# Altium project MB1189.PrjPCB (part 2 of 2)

## Sheet AUDIO2.SchDoc: Audio Codec and Microphone MEMS
size A4; Date: 9/24/2014; Author: P.A.; CompanyName: STMicroelectronics; Organization: Microcontrollers Division; Address1: 12, Rue Jules HOROWITZ; Address2: 38019 Grenoble; Address3: FRANCE; DocumentNumber: MB1189; Revision: B-07; SheetNumber: 6; SheetTotal: 12; Project: STM32F469I-DISCO
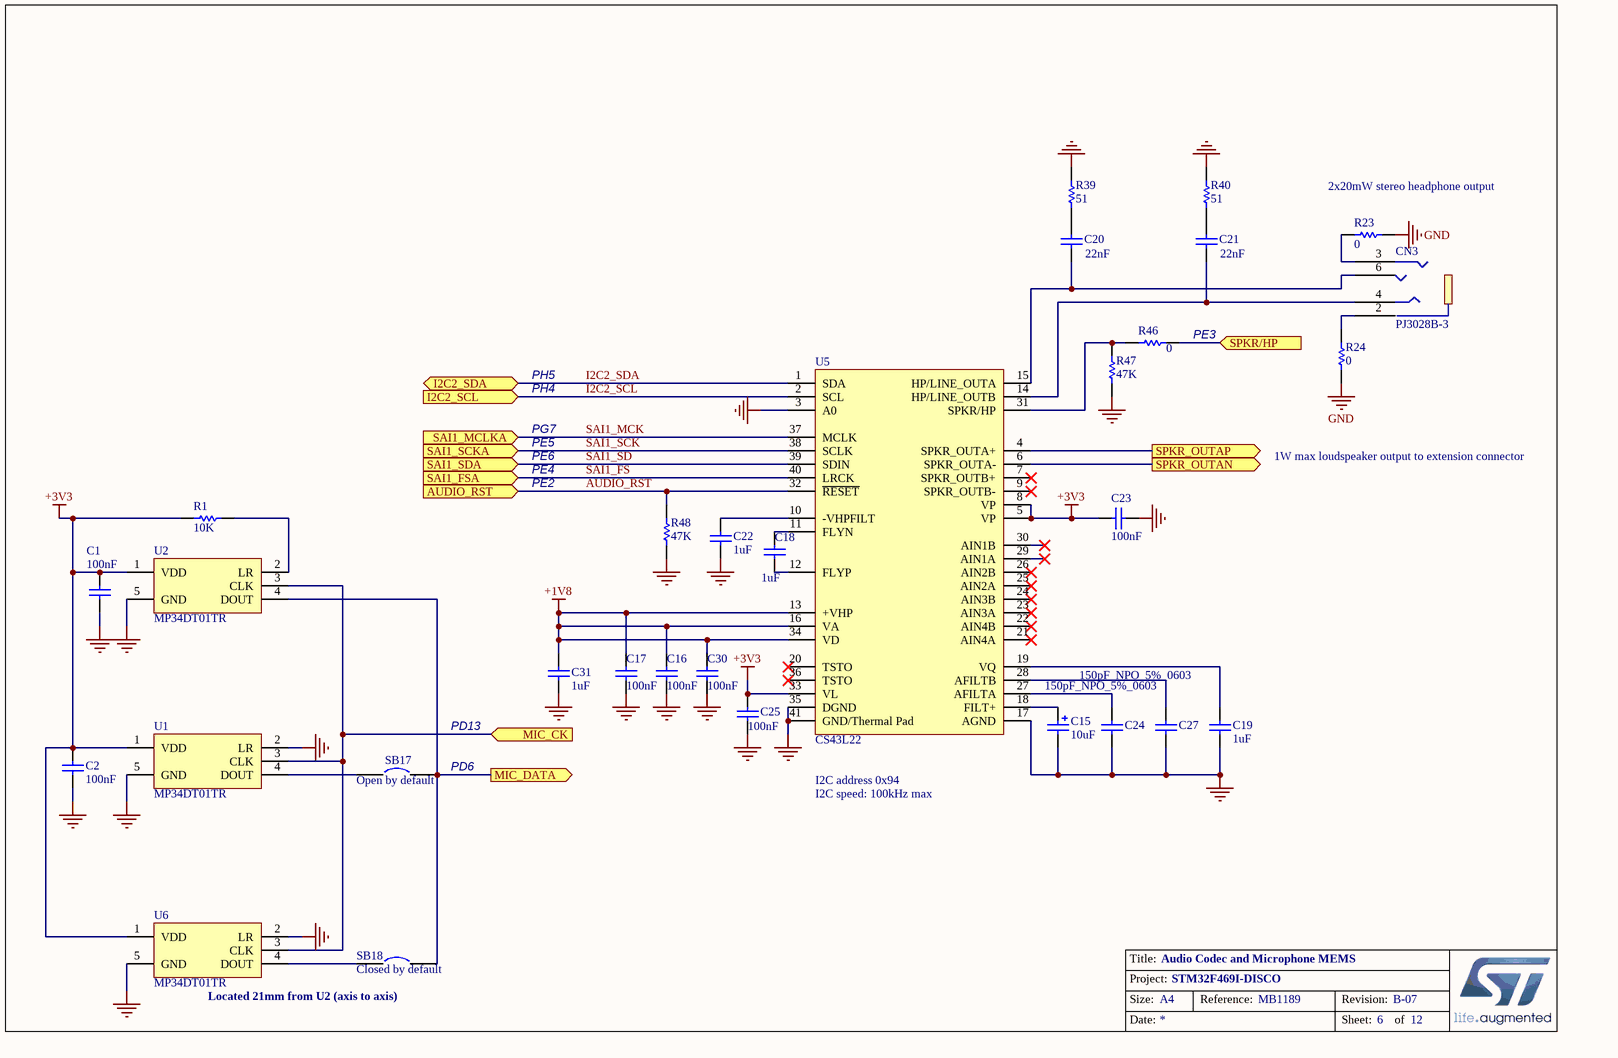
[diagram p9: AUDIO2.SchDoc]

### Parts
C1  100nF  [0402C]
C2  100nF  [0402C]
C15  10uF  [TAN-A]
C16  100nF  [0402C]
C17  100nF  [0402C]
C18  1uF  [0603C]
C19  1uF  [0603C]
C20  22nF  [0603C]
C21  22nF  [0603C]
C22  1uF  [0603C]
C23  100nF  [0402C]
C24  150pF_NPO_5%_0603  [0603C]
C25  100nF  [0402C]
C27  150pF_NPO_5%_0603  [0603C]
C30  100nF  [0402C]
C31  1uF  [0603C]
CN3  PJ3028B-3  [PJ3028B]
R1  10K  [0603R]
R23  0  [0603R]
R24  0  [0603R]
R39  51  [0402R]
R40  51  [0402R]
R46  0  [0603R]
R47  47K  [0603R]
R48  47K  [0603R]
SB17  Open by default  [SB_0603]
SB18  Closed by default  [SB_0603]
U1  MP34DT01TR  [MP34DT01TR]
U2  MP34DT01TR  [MP34DT01TR]
U5  CS43L22  [QFN40_0R5_6X6]
U6  MP34DT01TR  [MP34DT01TR]

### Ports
AUDIO_RST (in), I2C2_SCL (in), I2C2_SDA (bidir), MIC_CK (in), MIC_DATA (out), SAI1_FSA (in), SAI1_MCLKA (in), SAI1_SCKA (in), SAI1_SDA (in), SPKR/HP (in), SPKR_OUTAN (out), SPKR_OUTAP (out)

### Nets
+1V8: C16.1 C17.1 C30.1 C31.1 U5.13(+VHP) U5.16(VA) U5.34(VD)
+3V3: C1.2 C2.2 C23.2 C25.1 R1.2 U1.1(VDD) U2.1(VDD) U5.5(VP) U5.8(VP) U5.33(VL) U6.1(VDD)
GND: C1.1 C2.1 C15.2 C16.2 C17.2 C19.1 C22.1 C23.1 C24.1 C25.2 C27.1 C30.2 C31.2 R23.2 R24.2 R39.2 R40.2 R47.2 R48.1 U1.2(LR) U1.5(GND) U2.5(GND) U5.3(A0) U5.17(AGND) U5.35(DGND) U5.41(GND/Thermal_Pad) U6.2(LR) U6.5(GND)
AUDIO_RST: R48.2 U5.32(~{RESET}) ; port AUDIO_RST
I2C2_SCL: U5.2(SCL) ; port I2C2_SCL
I2C2_SDA: U5.1(SDA) ; port I2C2_SDA
PD6: SB17.2 SB18.2 U2.4(DOUT) ; port MIC_DATA
PE3: R46.2 ; port SPKR/HP
SAI1_FS: U5.40(LRCK) ; port SAI1_FSA  [project net PE4]
SAI1_MCK: U5.37(MCLK) ; port SAI1_MCLKA  [project net PG7]
SAI1_SCK: U5.38(SCLK) ; port SAI1_SCKA  [project net PE5]
SAI1_SD: U5.39(SDIN) ; port SAI1_SDA  [project net PE6]
SPKR_OUTAN: U5.6(SPKR_OUTA-) ; port SPKR_OUTAN
SPKR_OUTAP: U5.4(SPKR_OUTA+) ; port SPKR_OUTAP
NetC15_1: C15.1 U5.18(FILT+)
NetC18_1: C18.1 U5.11(FLYN)
NetC18_2: C18.2 U5.12(FLYP)
NetC19_2: C19.2 U5.19(VQ)
NetC20_1: C20.1 CN3.6 U5.15(HP/LINE_OUTA)
NetC20_2: C20.2 R39.1
NetC21_1: C21.1 CN3.4 U5.14(HP/LINE_OUTB)
NetC21_2: C21.2 R40.1
NetC22_2: C22.2 U5.10(-VHPFILT)
NetC24_2: C24.2 U5.27(AFILTA)
NetC27_2: C27.2 U5.28(AFILTB)
NetCN3_2: CN3.2 R24.1
NetCN3_3: CN3.3 R23.1
NetR1_1: R1.1 U2.2(LR)
NetR46_1: R46.1 R47.1 U5.31(SPKR/HP)
NetR87_1: U1.3(CLK) U2.3(CLK) U6.3(CLK) ; port MIC_CK
NetSB17_1: SB17.1 U1.4(DOUT)
NetSB18_1: SB18.1 U6.4(DOUT)

Not connected (* = marked no-connect by the designer): U5 7(SPKR_OUTB+)* 9(SPKR_OUTB-)* 20(TSTO)* 21(AIN4A)* 22(AIN4B)* 23(AIN3A)* 24(AIN3B)* 25(AIN2A)* 26(AIN2B)* 29(AIN1A)* 30(AIN1B)* 36(TSTO)*

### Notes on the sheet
- (near R23) 2x20mW stereo headphone output
- PH5
- (near R46) PE3
- PE5
- PG7
- PH4
- PE6
- PE4
- PE2
- 1W max loudspeaker output to extension connector
- PD13
- (near SB17) PD6
- I2C address 0x94
- I2C speed: 100kHz max
- Located 21mm from U2 (axis to axis)

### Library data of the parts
C1 C2 = Cap: Capacitor; Value: 10nF; Ordered by: Subcon
C15 = Cap Pol1: Polarized Capacitor (Radial); Ordered by: Subcon
C16-C19 C22 C23 C25 C30 C31 = CAP: Capacitor; Value: 100pF; Ordered by: Subcon
C20 C21 = Cap_22nF_X7R_10%_0603: Capacitor,22nF,50V,X7R,10%,0603,YAGEO; Manuf_Part_1: CC0603KRX7R9BB223; Ordered by: Subcon
C24 C27 = Cap_150pF_NPO_5%_0603: Capacitor,150pF,50V,NPO,5%,0603,YAGEO; Order: CC0603JRNPO9BN151; Ordered by: Subcon
CN3 = PJ3028B-3: Manuf_1: QIAOD; Ordered by: Subcon; Silkscreen: AUDIO JACK
R1 = Res_0_5%_0402: Resistor; Manuf_Part_1: RC0402JR-070RL; Manuf_1: YAGEO; Description: Resistor,0,0402,5%,YAGEO; Value: 0; Order: 2363467; Ordered by: Subcon
R23 R24 R46-R48 = Res1: Resistor; Value: 1K; Ordered by: Subcon
R39 R40 = Res_51_1%_0402: Resistor; Manuf_Part_1: RC0402FR-0751RL; Manuf_1: YAGEO; Description: Resistor,51,0402,1%,YAGEO; Order: 311-51.0LRTR-ND; Ordered by: Subcon
SB17 = Circuit Breaker: Ordered by: Subcon; Comments: Solder bridge; Fitted: NO
SB18 = Circuit Breaker: Ordered by: Subcon; Comments: Solder bridge
U1 U2 U6 = MP34DT01TR: MEMS audio sensor; Ordered by: ST; Ref St: 9188008; ECCN_US/EU: EAR99/NEC
U5 = CS43L22: Low Power, Stereo DAC w/Headphone & Speaker Amps; Manuf_1: Cirrus; Order: CS43L22-CNZ; ECCN_US/EU: EAR99/NEC; Ordered by: Subcon

## Sheet USB_OTG_FS.SchDoc: USB_OTG_FS
size A4; Date: 9/24/2014; Author: P.A.; CompanyName: STMicroelectronics; Organization: Microcontrollers Division; Address1: 12, Rue Jules HOROWITZ; Address2: 38019 Grenoble; Address3: FRANCE; DocumentNumber: MB1189; Revision: B-07; SheetNumber: 10; SheetTotal: 12; Project: STM32F469I-DISCO
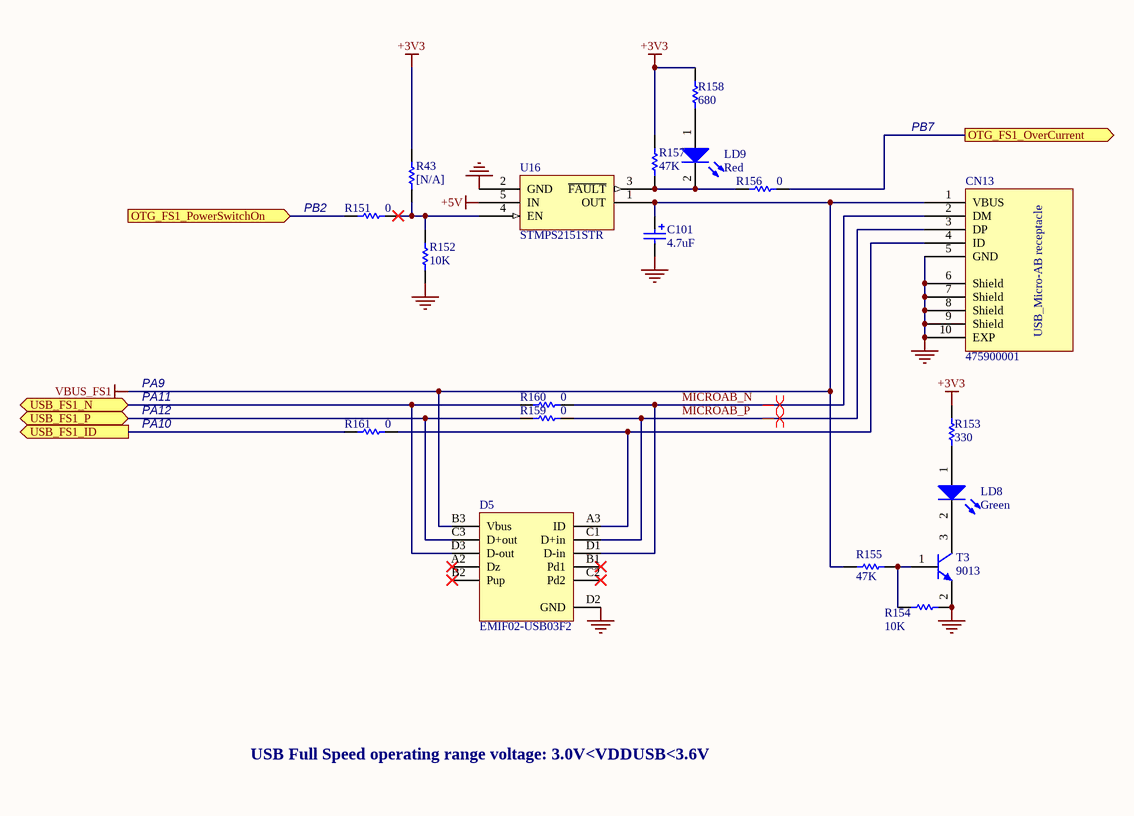
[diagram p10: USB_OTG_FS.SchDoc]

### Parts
C101  4.7uF  [TAN-A]
CN13  475900001  [MOLEX_47590001]
D5  EMIF02-USB03F2  [BGA11_0R5_1R57X2R07]
LD8  Green  [0603D]
LD9  Red  [0603D]
R43  [N/A]  [0603R]
R151  0  [0603R]
R152  10K  [0402R]
R153  330  [0603R]
R154  10K  [0603R]
R155  47K  [0603R]
R156  0  [0603R]
R157  47K  [0603R]
R158  680  [0603R]
R159  0  [0603R]
R160  0  [0603R]
R161  0  [0603R]
T3  9013  [SOT-23]
U16  STMPS2151STR  [SOT23-5]

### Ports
OTG_FS1_OverCurrent (out), OTG_FS1_PowerSwitchOn (in), USB_FS1_ID (out), USB_FS1_N (bidir), USB_FS1_P (bidir)

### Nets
+3V3: R43.1 R153.2 R157.1 R158.2
+5V: U16.5(IN)
GND: C101.2 CN13.5(GND) CN13.6(Shield) CN13.7(Shield) CN13.8(Shield) CN13.9(Shield) CN13.10(EXP) D5.D2(GND) R152.1 R154.1 T3.2(E) U16.2(GND)
VBUS_FS1: C101.1 CN13.1(VBUS) D5.B3(Vbus) R155.1 U16.1(OUT)
MICROAB_N: CN13.2(DM) D5.D1(D-in) R160.1
MICROAB_P: CN13.3(DP) D5.C1(D+in) R159.1
PA10: R161.2 ; port USB_FS1_ID
PB2: R151.2 ; port OTG_FS1_PowerSwitchOn
PB7: R156.1 ; port OTG_FS1_OverCurrent
USB_FS1_N: D5.D3(D-out) R160.2 ; port USB_FS1_N
USB_FS1_P: D5.C3(D+out) R159.2 ; port USB_FS1_P
NetCN13_4: CN13.4(ID) D5.A3(ID) R161.1
NetLD8_1: LD8.1(A) R153.1
NetLD8_2: LD8.2(K) T3.3(C)
NetLD9_1: LD9.1(A) R158.1
NetLD9_2: LD9.2(K) R156.2 R157.2 U16.3(~{FAULT})
NetR43_2: R43.2 R151.1 R152.2 U16.4(EN)
NetR154_2: R154.2 R155.2 T3.1(B)

Not connected (* = marked no-connect by the designer): D5 A2(Dz)* B1(Pd1)* B2(Pup)* C2(Pd2)*

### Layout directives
differential pair: MICROAB_N, MICROAB_P

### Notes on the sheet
- PB7
- (near R151) PB2
- PA9
- PA10
- PA11
- PA12
- USB Full Speed operating range voltage: 3.0V<VDDUSB<3.6V

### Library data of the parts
C101 = Cap Pol1: Polarized Capacitor (Radial); Value: 47uF; Ordered by: Subcon
CN13 = 475900001: Manuf_1: MOLEX; Ordered by: Subcon; Silkscreen: USB USER
D5 = EMIF02-USB03F2: 2-line IPAD, EMI filter including ESD protection; Manuf_1: ST; ECCN_US/EU: EAR99/NEC; Ref St: 9179037
LD8 = LED2: Typical RED, GREEN, YELLOW, AMBER GaAs LED; Ordered by: Subcon; ECCN_US/EU: EAR99/NEC; Silkscreen: VBUS
LD9 = LED2: Typical RED, GREEN, YELLOW, AMBER GaAs LED; Ordered by: Subcon; ECCN_US/EU: EAR99/NEC; Silkscreen: FAULT
R43 = Res1: Resistor; Value: 1K; Ordered by: Subcon; Fitted: NO
R151 R152 R156 R158-R161 = Res1: Resistor; Value: 1K; Ordered by: Subcon
R153-R155 R157 = res1: Resistor; Value: 1K; Ordered by: Subcon
T3 = NPN: NPN Bipolar Transistor; Manuf_Part_1: MMBT9013; Code - JEDEC: TO-226-AA; Ordered by: Subcon; ECCN_US/EU: EAR99/NEC
U16 = STMPS2141STR: Ordered by: ST; Ref St: 9159009; ECCN_US/EU: EAR99/NEC

## Sheet ExtensionConnector.SchDoc: Extension Connectors
size A4; Date: 9/24/2014; Author: P.A.; CompanyName: STMicroelectronics; Organization: Microcontrollers Division; Address1: 12, Rue Jules HOROWITZ; Address2: 38019 Grenoble; Address3: FRANCE; DocumentNumber: MB1189; Revision: B-07; SheetNumber: 3; SheetTotal: 12; Project: STM32F469I-DISCO
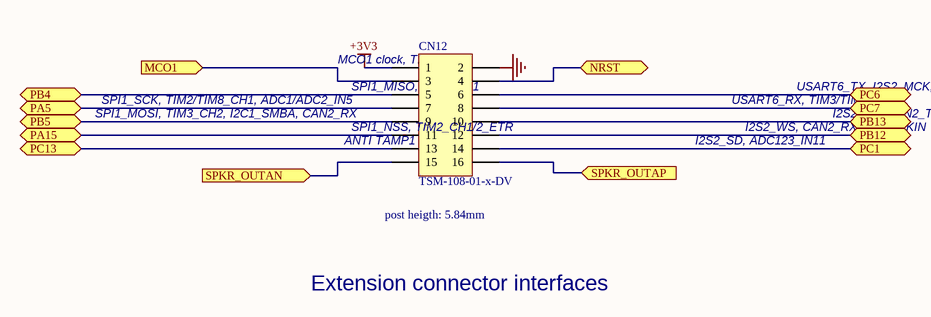
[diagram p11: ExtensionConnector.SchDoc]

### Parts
CN12  TSM-108-01-x-DV  [TSM-108-01-X-DV]

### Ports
MCO1 (in), NRST (bidir), PA5 (bidir), PA15 (bidir), PB4 (bidir), PB5 (bidir), PB12 (bidir), PB13 (bidir), PC1 (bidir), PC6 (bidir), PC7 (bidir), PC13 (bidir), SPKR_OUTAN (in), SPKR_OUTAP (in)

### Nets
+3V3: CN12.1
GND: CN12.2
NRST: CN12.4 ; port NRST
PA5: CN12.7 ; port PA5
PA8: CN12.3 ; port MCO1
PA15: CN12.11 ; port PA15
PB4: CN12.5 ; port PB4
PB5: CN12.9 ; port PB5
PB12: CN12.12 ; port PB12
PB13: CN12.10 ; port PB13
PC1: CN12.14 ; port PC1
PC6: CN12.6 ; port PC6
PC7: CN12.8 ; port PC7
PC13: CN12.13 ; port PC13
SPKR_OUTAN: CN12.15 ; port SPKR_OUTAN
SPKR_OUTAP: CN12.16 ; port SPKR_OUTAP

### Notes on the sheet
- MCO1 clock, TIM1_CH1
- SPI1_MISO, TIM3_CH1
- USART6_TX, I2S2_MCK, TIM3/TIM8_CH1
- SPI1_MOSI, TIM3_CH2, I2C1_SMBA, CAN2_RX
- SPI1_SCK, TIM2/TIM8_CH1, ADC1/ADC2_IN5
- ANTI TAMP1
- SPI1_NSS, TIM2_CH1/2_ETR
- I2S2_SD, ADC123_IN11
- USART6_RX, TIM3/TIM8_CH2
- I2S2_WS, CAN2_RX, TIM1_BKIN
- I2S2_CK, CAN2_TX, USART3_CTS, TIM1_CH1N
- (near CN12) post heigth: 5.84mm
- Extension connector interfaces

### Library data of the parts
CN12 = Header 8X2: Header, 8-Pin, Dual row; Manuf_1: SAMTEC; Ordered by: Subcon; Silkscreen: EXT

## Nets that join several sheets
+1V8: Power (C32.1 U8.2 U8.4), AUDIO2 (7 pins)
+3V3: Memory (28 pins), Peripherals (15 pins), Power (C41.1 JP5.1 SB8.2 U8.3), ST_LINK_V2-1 (R33.1), MCU (7 pins), Arduino_ Connectors (CN6.2 CN6.4), DSI_LCD (9 pins), QSPI (C62.1 R55.2 U12.8), AUDIO2 (11 pins), USB_OTG_FS (R43.1 R153.2 R157.1 R158.2), ExtensionConnector (CN12.1)
+5V: Power (6 pins), ST_LINK_V2-1 (D1.1), Arduino_ Connectors (CN6.5), DSI_LCD (L1.1 SB13.1), USB_OTG_FS (U16.5)
E5V: Power (C35.1 JP2.1 U10.2 U10.4), ST_LINK_V2-1 (D2.1)
GND: MB1189 (H1.1 H2.1 H3.1 H4.1), Memory (28 pins), Peripherals (7 pins), Power (12 pins), ST_LINK_V2-1 (34 pins), MCU (57 pins), Arduino_ Connectors (5 pins), DSI_LCD (12 pins), QSPI (C62.2 U12.4), AUDIO2 (28 pins), USB_OTG_FS (12 pins), ExtensionConnector (CN12.2)
U5V_ST_LINK: Power (JP2.3), ST_LINK_V2-1 (C14.2 U4.6 U4.7)
VBUS_FS1: Power (JP2.5), ST_LINK_V2-1 (D3.1), MCU (U14.E15), USB_OTG_FS (5 pins)
VDD_MCU: Power (JP5.2), MCU (40 pins)
VIN: Power (C36.1 U10.3), Arduino_ Connectors (CN6.8)
VREF+: MCU (C78.2 C80.1 R123.2 U14.P1), Arduino_ Connectors (C13.2 R41.1)
A0: Memory (U11.G8), MCU (U14.D2)
A1: Memory (U11.G9), MCU (U14.E2)
A2: Memory (U11.F7), MCU (U14.G2)
A3: Memory (U11.F3), MCU (U14.H2)
A4: Memory (U11.G1), MCU (U14.J2)
A5: Memory (U11.G2), MCU (U14.K3)
A6: Memory (U11.G3), MCU (U14.M6)
A7: Memory (U11.H1), MCU (U14.N6)
A8: Memory (U11.H2), MCU (U14.P6)
A9: Memory (U11.J3), MCU (U14.M8)
A10: Memory (U11.G7), MCU (U14.N7)
A11: Memory (U11.H9), MCU (U14.M7)
A14: Memory (U11.J7), MCU (U14.N12)
A15: Memory (U11.H8), MCU (U14.N11)
AUDIO_RST: MCU (U14.A3), AUDIO2 (R48.2 U5.32)
D0: Memory (TP4.1 U11.R8), MCU (TP1.1 U14.L12)
D1: Memory (U11.N7), MCU (U14.K13)
D2: Memory (U11.R9), MCU (U14.B12)
D3: Memory (U11.N8), MCU (U14.C12)
D4: Memory (U11.P9), MCU (U14.R8)
D5: Memory (U11.M8), MCU (U14.N9)
D6: Memory (U11.M7), MCU (U14.P9)
D7: Memory (U11.L8), MCU (U14.R9)
D8: Memory (U11.L2), MCU (U14.P10)
D9: Memory (U11.M3), MCU (U14.R10)
D10: Memory (U11.M2), MCU (U14.R12)
D11: Memory (U11.P1), MCU (U14.P11)
D12: Memory (U11.N2), MCU (U14.R11)
D13: Memory (U11.R1), MCU (U14.L15)
D14: Memory (U11.N3), MCU (U14.L14)
D15: Memory (U11.R2), MCU (U14.K15)
D16: Memory (U11.E8), MCU (U14.P14)
D17: Memory (U11.D7), MCU (U14.N14)
D18: Memory (U11.D8), MCU (U14.P15)
D19: Memory (U11.B9), MCU (U14.N15)
D20: Memory (U11.C8), MCU (U14.M15)
D21: Memory (U11.A9), MCU (U14.E12)
D22: Memory (U11.C7), MCU (U14.E13)
D23: Memory (U11.A8), MCU (U14.D13)
D24: Memory (U11.A2), MCU (U14.E14)
D25: Memory (U11.C3), MCU (U14.D14)
D26: Memory (U11.A1), MCU (U14.C14)
D27: Memory (U11.C2), MCU (U14.C13)
D28: Memory (U11.B1), MCU (U14.D6)
D29: Memory (U11.D2), MCU (U14.D4)
D30: Memory (U11.D3), MCU (U14.E4)
D31: Memory (U11.E2), MCU (U14.D5)
HSSI_CLK_N: MCU (U14.H13), DSI_LCD (CN10.12)
HSSI_CLK_P: MCU (U14.H12), DSI_LCD (CN10.14)
HSSI_D0_N: MCU (U14.J13), DSI_LCD (CN10.8)
HSSI_D0_P: MCU (U14.J12), DSI_LCD (CN10.10)
HSSI_D1_N: MCU (U14.F13), DSI_LCD (CN10.16)
HSSI_D1_P: MCU (U14.F12), DSI_LCD (CN10.18)
I2C1_SCL: Peripherals (CN11.3), MCU (R140.2 U14.A7), Arduino_ Connectors (CN5.10 SB11.1), DSI_LCD (CN2.3)
I2C1_SDA: Peripherals (CN11.1), MCU (R142.2 U14.B4), Arduino_ Connectors (CN5.9 SB9.1), DSI_LCD (CN2.4)
I2C2_SCL: MCU (R121.2 U14.H4), AUDIO2 (U5.2)
I2C2_SDA: MCU (R124.2 U14.J3), AUDIO2 (U5.1)
LCD_BL_CTRL: MCU (U14.R2), DSI_LCD (R119.2)
LCD_INT: MCU (U14.M14), DSI_LCD (CN2.2 R36.2)
LCD_RST: MCU (U14.N13), DSI_LCD (CN2.5 CN10.5 R34.2)
NetC26_1: ST_LINK_V2-1 (C26.1 R35.2), MCU (SB19.1)
NetCN9_8: Peripherals (CN9.8 R86.2), MCU (R135.2)
NetR87_1: MCU (R87.1), AUDIO2 (U1.3 U2.3 U6.3)
NetSB3_2: ST_LINK_V2-1 (SB3.2), MCU (SB7.1)
NRST: Peripherals (SB1.1), ST_LINK_V2-1 (SB2.2), MCU (U14.J1), Arduino_ Connectors (CN6.3), ExtensionConnector (CN12.4)
PA0: Peripherals (R18.2), MCU (U14.N3)
PA1: MCU (U14.N2), Arduino_ Connectors (CN7.4)
PA2: MCU (U14.P2), Arduino_ Connectors (CN7.6)
PA4: MCU (U14.N4), Arduino_ Connectors (SB12.1)
PA5: MCU (U14.P4), ExtensionConnector (CN12.7)
PA6: MCU (U14.P3), Arduino_ Connectors (CN7.7)
PA7: MCU (U14.R3), Arduino_ Connectors (CN5.2)
PA8: MCU (U14.F15), ExtensionConnector (CN12.3)
PA10: MCU (U14.D15), USB_OTG_FS (R161.2)
PA13: ST_LINK_V2-1 (R20.2 U3.27), MCU (U14.A15)
PA14: ST_LINK_V2-1 (U3.15 U3.26), MCU (U14.A14)
PA15: MCU (U14.A13), ExtensionConnector (CN12.11)
PB0: Peripherals (CN11.4), MCU (U14.R5)
PB1: MCU (U14.R4), Arduino_ Connectors (CN8.1)
PB2: MCU (U14.M5), USB_OTG_FS (R151.2)
PB4: MCU (U14.A9), ExtensionConnector (CN12.5)
PB5: MCU (U14.A8), ExtensionConnector (CN12.9)
PB6: MCU (U14.B6), QSPI (R55.1 U12.1)
PB7: MCU (U14.B5), USB_OTG_FS (R156.1)
PB10: ST_LINK_V2-1 (U3.13), MCU (U14.P12)
PB11: ST_LINK_V2-1 (U3.12), MCU (U14.R13)
PB12: MCU (U14.L13), ExtensionConnector (CN12.12)
PB13: MCU (U14.K14), ExtensionConnector (CN12.10)
PB14: MCU (U14.R14), Arduino_ Connectors (CN5.5)
PB15: MCU (U14.R15), Arduino_ Connectors (CN5.4)
PC0: Memory (TP2.1 U11.K8), MCU (U14.M2)
PC1: MCU (U14.M3), ExtensionConnector (CN12.14)
PC2: MCU (U14.M4), Arduino_ Connectors (CN8.2)
PC3: MCU (U14.L4), Arduino_ Connectors (CN8.3)
PC4: MCU (U14.N5), Arduino_ Connectors (CN8.4)
PC5: MCU (U14.P5), Arduino_ Connectors (SB10.1)
PC6: MCU (U14.H15), ExtensionConnector (CN12.6)
PC7: MCU (U14.G15), ExtensionConnector (CN12.8)
PC8: Peripherals (CN9.7 R114.2), MCU (U14.G14)
PC10: Peripherals (CN9.1 R120.2), MCU (U14.B14)
PC11: Peripherals (CN9.2 R116.2), MCU (U14.B13)
PC12: Peripherals (CN9.5), MCU (U14.A12)
PC13: MCU (U14.D1), ExtensionConnector (CN12.13)
PD2: Peripherals (CN9.3 R115.2), MCU (U14.D12)
PD3: MCU (U14.C11), Arduino_ Connectors (CN5.6 SB5.2)
PD4: Peripherals (R3.1), MCU (U14.D11)
PD5: Peripherals (R4.1), MCU (U14.C10)
PD6: MCU (U14.B11), AUDIO2 (SB17.2 SB18.2 U2.4)
PE0: Memory (U11.K9), MCU (U14.A6)
PE1: Memory (U11.K1), MCU (U14.A5)
PE3: MCU (U14.A2), AUDIO2 (R46.2)
PE4: MCU (U14.A1), AUDIO2 (U5.40)
PE5: MCU (U14.B1), AUDIO2 (U5.38)
PE6: MCU (U14.B2), AUDIO2 (U5.39)
PF6: MCU (U14.K2), QSPI (U12.7)
PF7: MCU (U14.K1), QSPI (U12.3)
PF8: MCU (U14.L3), QSPI (TP6.1 U12.5)
PF9: MCU (U14.L2), QSPI (TP7.1 U12.2)
PF10: MCU (U14.L1), QSPI (TP5.1 U12.6)
PF11: Memory (U11.J9), MCU (U14.P8)
PG2: Peripherals (R57.1), MCU (U14.M13)
PG6: Peripherals (R2.1), MCU (U14.J15)
PG7: MCU (U14.J14), AUDIO2 (U5.37)
PG8: Memory (TP3.1 U11.J1), MCU (U14.H14)
PG9: MCU (U14.D9), Arduino_ Connectors (CN7.1)
PG10: MCU (U14.C8), Arduino_ Connectors (CN5.1)
PG11: MCU (U14.B8), Arduino_ Connectors (CN7.8)
PG12: MCU (U14.C7), Arduino_ Connectors (CN7.5)
PG13: MCU (U14.B3), Arduino_ Connectors (CN7.3)
PG14: MCU (U14.A4), Arduino_ Connectors (CN7.2)
PG15: Memory (U11.K7), MCU (U14.B7)
PH2: Memory (U11.J2), MCU (U14.K4)
PH3: Memory (U11.J8), MCU (U14.J4)
PH6: MCU (U14.P13), Arduino_ Connectors (CN5.3)
PI4: Memory (U11.F8), MCU (U14.C3)
PI5: Memory (U11.F2), MCU (U14.D3)
PJ2: MCU (U14.P7), DSI_LCD (CN10.22)
PK3: Peripherals (R5.1), MCU (U14.D8)
SPKR_OUTAN: AUDIO2 (U5.6), ExtensionConnector (CN12.15)
SPKR_OUTAP: AUDIO2 (U5.4), ExtensionConnector (CN12.16)
USB_FS1_N: MCU (U14.C15), USB_OTG_FS (D5.D3 R160.2)
USB_FS1_P: MCU (U14.B15), USB_OTG_FS (D5.C3 R159.2)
